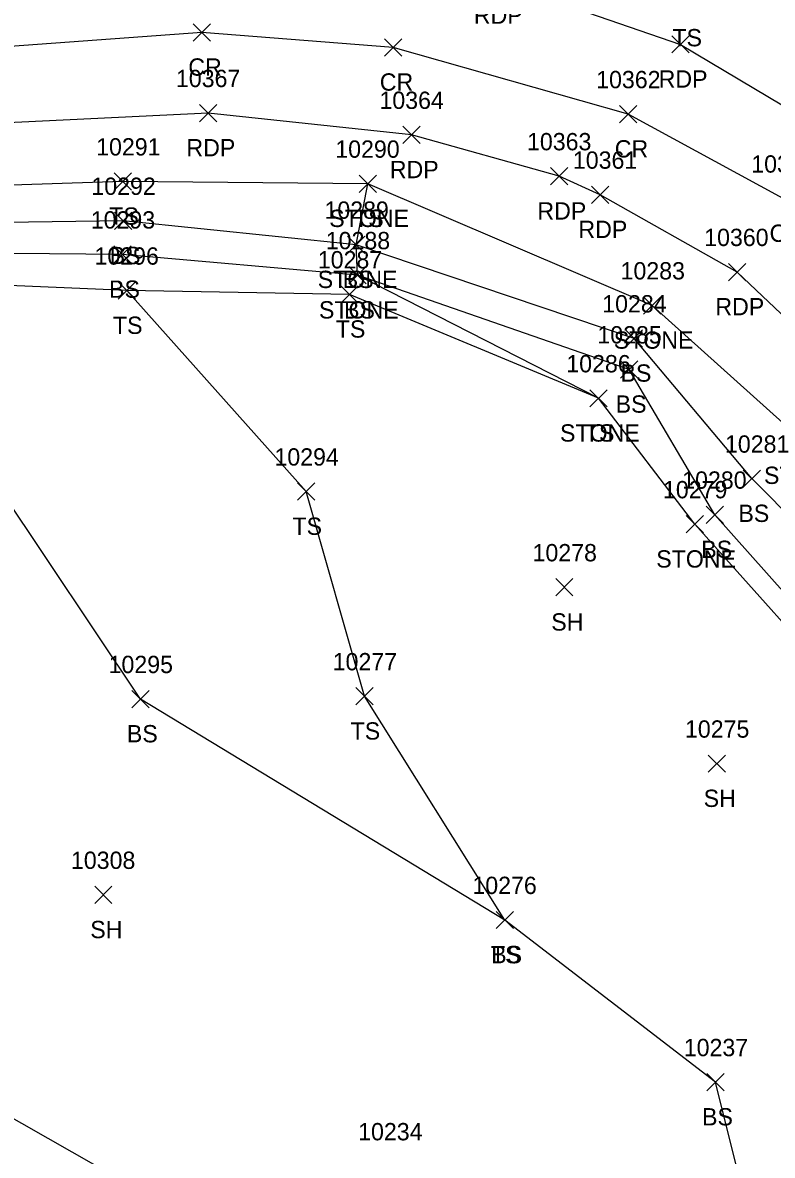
# Model space of a CAD drawing. Extents: x 1475671 to 1477951, y 592661 to 593821.
# Drawn here: x 1476740.9 to 1476827.5, y 592957 to 593087.8 of the extents above; entities that cross this region are included whole.
import ezdxf

# ---------------------------------------------------------------- set-up
doc = ezdxf.new("R2010")
doc.units = 0
for name, color, linetype in [('L_A', 7, 'Continuous'), ('L_I', 7, 'Continuous'), ('L_TIC', 7, 'Continuous'), ('LASF', 7, 'Continuous'), ('LELB', 7, 'Continuous'), ('P_A', 7, 'Continuous'), ('P_I', 7, 'Continuous'), ('P_TIC', 7, 'Continuous'), ('PET', 7, 'Continuous'), ('PRC', 7, 'Continuous')]:
    doc.layers.add(name, color=color, linetype=linetype)

msp = doc.modelspace()

# ---------------------------------------------------------------- linework, layer by layer
at = {"layer": 'L_TIC'}
for points in [[(1476751.47, 593068.45), (1476753.47, 593070.45)], [(1476753.47, 593068.45), (1476751.47, 593070.45)], [(1476779.76, 593068.19), (1476781.76, 593070.19)], [(1476781.76, 593068.19), (1476779.76, 593070.19)], [(1476779.76, 593068.19), (1476781.76, 593070.19)], [(1476781.76, 593068.19), (1476779.76, 593070.19)], [(1476779.76, 593068.19), (1476781.76, 593070.19)], [(1476781.76, 593068.19), (1476779.76, 593070.19)], [(1476751.49, 593063.9), (1476753.49, 593065.9)], [(1476753.49, 593063.9), (1476751.49, 593065.9)], [(1476778.42, 593061.14), (1476780.42, 593063.14)], [(1476780.42, 593061.14), (1476778.42, 593063.14)], [(1476778.42, 593061.14), (1476780.42, 593063.14)], [(1476780.42, 593061.14), (1476778.42, 593063.14)], [(1476751.41, 593060.01), (1476753.41, 593062.01)], [(1476753.41, 593060.01), (1476751.41, 593062.01)], [(1476778.57, 593057.62), (1476780.57, 593059.62)], [(1476780.57, 593057.62), (1476778.57, 593059.62)], [(1476778.57, 593057.62), (1476780.57, 593059.62)], [(1476780.57, 593057.62), (1476778.57, 593059.62)], [(1476751.9, 593055.84), (1476753.9, 593057.84)], [(1476753.9, 593055.84), (1476751.9, 593057.84)], [(1476751.9, 593055.84), (1476753.9, 593057.84)], [(1476753.9, 593055.84), (1476751.9, 593057.84)], [(1476777.65, 593055.41), (1476779.65, 593057.41)], [(1476779.65, 593055.41), (1476777.65, 593057.41)], [(1476812.62, 593054.13), (1476814.62, 593056.13)], [(1476814.62, 593054.13), (1476812.62, 593056.13)], [(1476810.51, 593050.32), (1476812.51, 593052.32)], [(1476812.51, 593050.32), (1476810.51, 593052.32)], [(1476809.95, 593046.74), (1476811.95, 593048.74)], [(1476811.95, 593046.74), (1476809.95, 593048.74)], [(1476806.42, 593043.4), (1476808.42, 593045.4)], [(1476808.42, 593043.4), (1476806.42, 593045.4)], [(1476806.42, 593043.4), (1476808.42, 593045.4)], [(1476808.42, 593043.4), (1476806.42, 593045.4)], [(1476824.12, 593034.12), (1476826.12, 593036.12)], [(1476826.12, 593034.12), (1476824.12, 593036.12)], [(1476772.64, 593032.63), (1476774.64, 593034.63)], [(1476774.64, 593032.63), (1476772.64, 593034.63)], [(1476819.84, 593029.96), (1476821.84, 593031.96)], [(1476821.84, 593029.96), (1476819.84, 593031.96)], [(1476817.53, 593028.85), (1476819.53, 593030.85)], [(1476819.53, 593028.85), (1476817.53, 593030.85)], [(1476802.46, 593021.57), (1476804.46, 593023.57)], [(1476804.46, 593021.57), (1476802.46, 593023.57)], [(1476753.48, 593008.66), (1476755.48, 593010.66)], [(1476755.48, 593008.66), (1476753.48, 593010.66)], [(1476779.37, 593008.98), (1476781.37, 593010.98)], [(1476781.37, 593008.98), (1476779.37, 593010.98)], [(1476820.07, 593001.2), (1476822.07, 593003.2)], [(1476822.07, 593001.2), (1476820.07, 593003.2)], [(1476749.2, 592986.04), (1476751.2, 592988.04)], [(1476751.2, 592986.04), (1476749.2, 592988.04)], [(1476795.57, 592983.14), (1476797.57, 592985.14)], [(1476797.57, 592983.14), (1476795.57, 592985.14)], [(1476795.57, 592983.14), (1476797.57, 592985.14)], [(1476797.57, 592983.14), (1476795.57, 592985.14)], [(1476819.93, 592964.41), (1476821.93, 592966.41)], [(1476821.93, 592964.41), (1476819.93, 592966.41)]]:
    msp.add_lwpolyline(points, dxfattribs=at)
at = {"layer": 'LASF'}
for points in [[(1476852.6, 593006.17), (1476849.63, 593004.41), (1476846.68, 593002.44), (1476843.57, 593001.16), (1476837.13, 593009.09), (1476818.53, 593029.85), (1476807.42, 593044.4), (1476779.57, 593058.62), (1476779.42, 593062.14), (1476780.76, 593069.19)], [(1476852.6, 593006.17), (1476847.62, 593014.72), (1476844.58, 593021.3), (1476830.99, 593039.51), (1476813.62, 593055.13), (1476780.76, 593069.19)]]:
    msp.add_lwpolyline(points, dxfattribs=at)
at = {"layer": 'LELB'}
for points in [[(1476780.76, 593069.19), (1476752.47, 593069.45), (1476722.06, 593068.43), (1476689.75, 593062.22), (1476665.64, 593056.95), (1476659.84, 593058), (1476658.42, 593059.61), (1476656.72, 593061.12)], [(1476841.85, 593018.32), (1476825.12, 593035.12), (1476811.51, 593051.32), (1476779.42, 593062.14), (1476752.49, 593064.9), (1476722.37, 593064.49), (1476691.91, 593057.79), (1476666.49, 593052.08), (1476661.25, 593053.21), (1476656.95, 593052.9), (1476655.98, 593055.35), (1476654.36, 593057.56), (1476652.4, 593057.3), (1476651.11, 593057.01), (1476646.46, 593054.41), (1476629, 593052.03), (1476594.01, 593046.66), (1476557.34, 593044.4), (1476521.14, 593041.18), (1476464.22, 593030.64)], [(1476839.39, 593010.15), (1476820.84, 593030.96), (1476810.95, 593047.74), (1476779.57, 593058.62), (1476752.41, 593061.01), (1476722.8, 593061.3), (1476693.96, 593054.33), (1476667.9, 593046.42), (1476659.43, 593048.7), (1476654.11, 593050.55), (1476650.93, 593054.11), (1476646.9, 593052.35), (1476629.79, 593048.23), (1476596.33, 593042), (1476591.8, 593026.06), (1476582.27, 593023.28), (1476575.03, 593016.09), (1476569.43, 592997.76), (1476547.37, 592959.22)], [(1476807.42, 593044.4), (1476778.65, 593056.41), (1476752.9, 593056.84), (1476722.03, 593058.18), (1476696.31, 593050.53), (1476668.87, 593043.24), (1476656.59, 593046.41), (1476650.8, 593042.11), (1476638.89, 593026.04), (1476625.94, 593005.7), (1476601.98, 592989.57), (1476589.47, 592942.63), (1476588.41, 592908.01)], [(1476827.26, 592834.12), (1476835.32, 592879.17), (1476841.26, 592896.75), (1476832.77, 592915.24), (1476825.78, 592945.91), (1476820.93, 592965.41), (1476796.57, 592984.14), (1476754.48, 593009.66), (1476722.03, 593058.18)], [(1476796.57, 592984.14), (1476780.37, 593009.98), (1476773.64, 593033.63), (1476752.9, 593056.84)], [(1476850.04, 592796.99), (1476834.85, 592814.45), (1476832.4, 592817.5), (1476827.26, 592834.12), (1476804.05, 592871.04), (1476800.09, 592907.29), (1476764.33, 592947.22), (1476734.93, 592963.95), (1476717.53, 592992.71), (1476686.74, 592992.91), (1476656.64, 592987.69)]]:
    msp.add_lwpolyline(points, dxfattribs=at)
at = {"layer": 'P_TIC'}
for points in [[(1476760.58, 593085.67), (1476762.58, 593087.67)], [(1476762.58, 593085.67), (1476760.58, 593087.67)], [(1476782.7, 593083.94), (1476784.7, 593085.94)], [(1476784.7, 593083.94), (1476782.7, 593085.94)], [(1476782.7, 593083.94), (1476784.7, 593085.94)], [(1476784.7, 593083.94), (1476782.7, 593085.94)], [(1476815.88, 593084.29), (1476817.88, 593086.29)], [(1476817.88, 593084.29), (1476815.88, 593086.29)], [(1476761.31, 593076.35), (1476763.31, 593078.35)], [(1476763.31, 593076.35), (1476761.31, 593078.35)], [(1476809.85, 593076.22), (1476811.85, 593078.22)], [(1476811.85, 593076.22), (1476809.85, 593078.22)], [(1476784.81, 593073.83), (1476786.81, 593075.83)], [(1476786.81, 593073.83), (1476784.81, 593075.83)], [(1476801.87, 593069.05), (1476803.87, 593071.05)], [(1476803.87, 593069.05), (1476801.87, 593071.05)], [(1476806.6, 593066.92), (1476808.6, 593068.92)], [(1476808.6, 593066.92), (1476806.6, 593068.92)], [(1476822.42, 593057.99), (1476824.42, 593059.99)], [(1476824.42, 593057.99), (1476822.42, 593059.99)]]:
    msp.add_lwpolyline(points, dxfattribs=at)
at = {"layer": 'PET'}
for points in [[(1476550.12, 593088.22), (1476546.99, 593080.79), (1476546.62, 593074.3), (1476558.02, 593070.45), (1476566.6, 593070.83), (1476605.7, 593074.02), (1476651.65, 593078.89), (1476683.81, 593086.28), (1476716.78, 593091.72), (1476756.3, 593096.32), (1476786.76, 593094.61), (1476795.52, 593092.66), (1476816.88, 593085.29), (1476835.43, 593074.22), (1476828.62, 593102.02), (1476824.42, 593119.75), (1476821.59, 593140.77), (1476821.02, 593163.56), (1476821.92, 593180.44), (1476827.12, 593207.84), (1476837.47, 593243.39), (1476848.83, 593278.3), (1476858.44, 593303.19), (1476868.19, 593333.86)], [(1476876.69, 592931.37), (1476866.39, 592975.94), (1476855.42, 593012.87), (1476851.35, 593023.14), (1476844.63, 593035.78), (1476834.27, 593048.7), (1476823.42, 593058.99), (1476807.6, 593067.92), (1476802.87, 593070.05), (1476785.81, 593074.83), (1476762.31, 593077.35), (1476735.17, 593076.04), (1476692.75, 593070.03), (1476654.27, 593063.28), (1476593.38, 593051.4), (1476557.14, 593047.34), (1476521.33, 593044.37), (1476462.5, 593038.2)]]:
    msp.add_lwpolyline(points, dxfattribs=at)
at = {"layer": 'PRC'}
for points in [[(1476783.7, 593084.94), (1476761.58, 593086.67), (1476734.11, 593084.66), (1476691.9, 593077.87), (1476653.54, 593071.49), (1476592.22, 593062.91), (1476555.36, 593059.5), (1476520.45, 593058.11), (1476501.29, 593059.51), (1476493.61, 593061.9)], [(1476936.41, 592672.33), (1476928.58, 592713.02), (1476920.34, 592755.64), (1476913.25, 592793.06), (1476905.79, 592835.15), (1476893.85, 592896.99), (1476886.39, 592933.64), (1476875.73, 592978.34), (1476865.02, 593017.01), (1476853.41, 593046.52), (1476843.49, 593055.1), (1476828.74, 593067.47), (1476810.85, 593077.22), (1476783.7, 593084.94)]]:
    msp.add_lwpolyline(points, dxfattribs=at)

# ---------------------------------------------------------------- texts
at = {"layer": 'L_A'}
for s, p in [('TS', (1476815.95, 593085.06)), ('TS', (1476750.88, 593064.45)), ('STONE', (1476776.3, 593064.19)), ('STONE', (1476776.3, 593064.19)), ('TS', (1476779.17, 593064.19)), ('BS', (1476750.93, 593059.9)), ('STONE', (1476774.97, 593057.14)), ('BS', (1476777.86, 593057.14)), ('BS', (1476750.86, 593056.01)), ('STONE', (1476775.11, 593053.62)), ('BS', (1476778.01, 593053.62)), ('TS', (1476751.31, 593051.84)), ('TS', (1476751.31, 593051.84)), ('TS', (1476777.06, 593051.41)), ('STONE', (1476809.17, 593050.13)), ('BS', (1476809.95, 593046.32)), ('BS', (1476809.39, 593042.74)), ('STONE', (1476802.96, 593039.4)), ('TS', (1476805.83, 593039.4)), ('STONE', (1476826.53, 593034.51)), ('BS', (1476823.57, 593030.12)), ('TS', (1476772.05, 593028.63)), ('BS', (1476819.28, 593025.96)), ('STONE', (1476814.08, 593024.85)), ('SH', (1476801.95, 593017.57)), ('BS', (1476752.92, 593004.66)), ('TS', (1476778.77, 593004.98)), ('SH', (1476819.56, 592997.2)), ('SH', (1476748.69, 592982.04)), ('TS', (1476794.98, 592979.14)), ('BS', (1476795.01, 592979.14)), ('BS', (1476819.37, 592960.41))]:
    msp.add_text(s, height=2, dxfattribs=at).set_placement(p)
at = {"layer": 'L_I'}
for s, p in [('10291', (1476749.37, 593072.45)), ('10290', (1476777, 593072.19)), ('10290', (1476777, 593072.19)), ('10290', (1476777, 593072.19)), ('10292', (1476748.82, 593067.9)), ('10289', (1476775.75, 593065.14)), ('10289', (1476775.75, 593065.14)), ('10293', (1476748.75, 593064.01)), ('10288', (1476775.9, 593061.62)), ('10288', (1476775.9, 593061.62)), ('10296', (1476749.18, 593059.84)), ('10296', (1476749.18, 593059.84)), ('10287', (1476774.98, 593059.41)), ('10283', (1476809.96, 593058.13)), ('10284', (1476807.84, 593054.32)), ('10285', (1476807.28, 593050.74)), ('10286', (1476803.69, 593047.4)), ('10286', (1476803.69, 593047.4)), ('10281', (1476822.02, 593038.12)), ('10294', (1476769.97, 593036.63)), ('10279', (1476814.86, 593032.85)), ('10280', (1476817.08, 593033.96)), ('10278', (1476799.79, 593025.57)), ('10295', (1476750.81, 593012.66)), ('10277', (1476776.7, 593012.98)), ('10275', (1476817.4, 593005.2)), ('10308', (1476746.46, 592990.04)), ('10276', (1476792.84, 592987.14)), ('10276', (1476792.84, 592987.14)), ('10237', (1476817.26, 592968.41)), ('10234', (1476779.64, 592958.69))]:
    msp.add_text(s, height=2, dxfattribs=at).set_placement(p)
at = {"layer": 'P_A'}
for s, p in [('RDP', (1476793.01, 593087.66)), ('CR', (1476760.02, 593081.67)), ('CR', (1476782.14, 593079.94)), ('CR', (1476782.14, 593079.94)), ('RDP', (1476814.36, 593080.29)), ('RDP', (1476759.8, 593072.35)), ('CR', (1476809.29, 593072.22)), ('RDP', (1476783.3, 593069.83)), ('RDP', (1476800.35, 593065.05)), ('RDP', (1476805.09, 593062.92)), ('CR', (1476827.17, 593062.47)), ('RDP', (1476820.91, 593053.99))]:
    msp.add_text(s, height=2, dxfattribs=at).set_placement(p)
at = {"layer": 'P_I'}
for s, p in [('10367', (1476758.59, 593080.35)), ('10362', (1476807.14, 593080.22)), ('10364', (1476782.1, 593077.83)), ('10363', (1476799.15, 593073.05)), ('10361', (1476804.45, 593070.92)), ('10359', (1476825.06, 593070.47)), ('10360', (1476819.62, 593061.99))]:
    msp.add_text(s, height=2, dxfattribs=at).set_placement(p)

doc.saveas('drawing.dxf')
